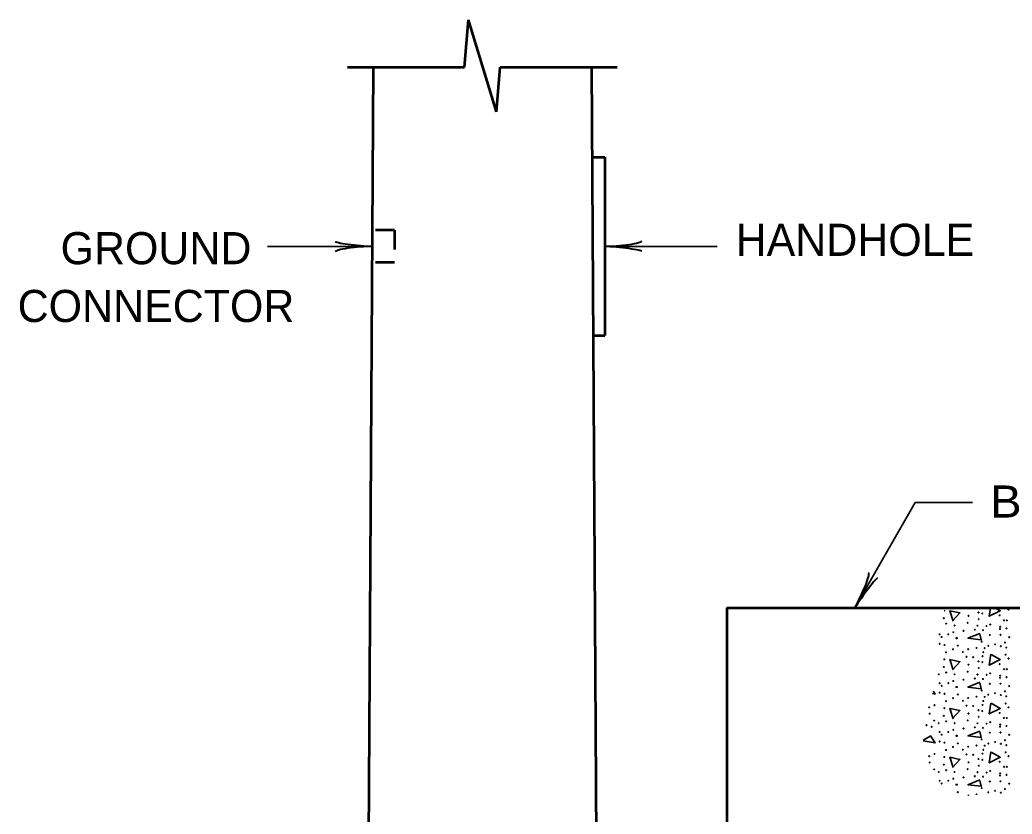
# Model space of a CAD drawing. Extents: x -35 to 821, y -23 to 522.
# Drawn here: x 313.6 to 406.3, y 208.5 to 282.7 of the extents above; entities that cross this region are included whole.
import ezdxf
from ezdxf.enums import TextEntityAlignment as Align

# ---------------------------------------------------------------- set-up
doc = ezdxf.new("R2010")
doc.units = 0
doc.header["$LTSCALE"] = 1.2
doc.linetypes.add('SHORT_DASHED', pattern=[2.7, 1.5, -1.2])
doc.layers.add('1', color=7, linetype='Continuous', lineweight=35)

msp = doc.modelspace()

# ---------------------------------------------------------------- linework, layer by layer
at = {"layer": '1', "lineweight": 53}
for p, q in [((355.139, 278.3), (355.526, 282.729)), ((358.12, 274.128), (355.526, 282.729)), ((344.212, 278.3), (355.139, 278.3)), ((346.612, 278.3), (346.008, 175.593)), ((358.12, 274.128), (358.485, 278.3)), ((358.485, 278.3), (369.412, 278.3)), ((367.012, 278.3), (367.617, 175.564)), ((367.062, 269.897), (368.262, 269.897)), ((368.262, 269.897), (368.262, 253.242)), ((367.16, 253.242), (368.262, 253.242)), ((379.645, 227.82), (379.645, 144.588)), ((379.645, 227.82), (400.045, 227.82))]:
    msp.add_line(p, q, dxfattribs=at)
at = {"layer": '1', "linetype": 'SHORT_DASHED', "lineweight": 53}
for p, q in [((348.614, 263.07), (346.514, 263.07)), ((348.614, 263.07), (348.614, 260.07)), ((348.614, 260.07), (346.514, 260.07))]:
    msp.add_line(p, q, dxfattribs=at)
at = {"layer": '1'}
for p, q in [((346.514, 261.57), (336.727, 261.57)), ((368.262, 261.57), (378.744, 261.57)), ((398.723, 215.843), (398.007, 215.453))]:
    msp.add_line(p, q, dxfattribs=at)
for points in [[(391.622, 227.82), (397.262, 237.643), (402.619, 237.643)], [(400.787, 226.571), (400.499, 227.531), (401.435, 227.339), (400.763, 226.619)], [(404.697, 227.82), (405.203, 227.531), (404.171, 227.027), (404.284, 227.82)], [(403.307, 225.419), (402.179, 224.963), (403.427, 224.819), (403.307, 225.371)], [(404.363, 223.451), (405.203, 222.971), (404.171, 222.467), (404.315, 223.475)], [(400.787, 222.011), (400.499, 222.971), (401.435, 222.779), (400.763, 222.059)], [(403.307, 220.859), (402.179, 220.403), (403.427, 220.259), (403.307, 220.811)], [(398.868, 219.799), (399.107, 219.755), (398.927, 220.035)], [(404.363, 218.891), (405.203, 218.411), (404.171, 217.907), (404.315, 218.915)], [(400.787, 217.451), (400.499, 218.411), (401.435, 218.219), (400.763, 217.499)], [(403.307, 216.299), (402.179, 215.843), (403.427, 215.699), (403.307, 216.251)], [(398.006, 215.397), (399.107, 215.195), (398.675, 215.867)], [(404.363, 214.331), (405.203, 213.851), (404.171, 213.347), (404.315, 214.355)], [(400.787, 212.891), (400.499, 213.851), (401.435, 213.659), (400.763, 212.939)], [(403.307, 211.739), (402.179, 211.283), (403.427, 211.139), (403.307, 211.691)]]:
    msp.add_lwpolyline(points, dxfattribs=at)
at = {"layer": '1', "lineweight": 53}
msp.add_lwpolyline([(400.045, 227.82), (410.845, 227.82), (412.644, 226.02), (415.449, 211.896)], dxfattribs=at)
at = {"layer": '1'}
for centre in [(402.665, 227.766), (403.174, 227.368), (403.524, 227.289), (405.973, 227.638), (399.93, 226.843), (400.153, 226.334), (402.157, 226.414), (402.236, 227.066), (403.19, 226.748), (404.256, 226.254), (405.146, 227.114), (405.544, 226.636), (405.814, 226.636), (399.532, 225.338), (400.344, 225.338), (400.821, 225.529), (400.932, 226.159), (401.759, 225.656), (402.825, 225.767), (403.079, 226.143), (403.588, 225.719), (403.922, 226.111), (404.224, 225.274), (405.178, 225.831), (405.194, 226.032), (405.226, 225.29), (405.783, 225.894), (399.532, 224.447), (399.723, 225.083), (401.091, 224.972), (401.155, 224.972), (403.461, 224.653), (404.717, 224.399), (405.639, 224.574), (406.037, 225.067), (399.994, 224.335), (400.137, 223.651), (400.789, 223.938), (401.234, 224.272), (401.711, 223.683), (402.204, 223.954), (402.984, 224.065), (403.62, 223.667), (403.747, 224.049), (404.081, 224.256), (405.258, 224.224), (405.703, 223.429), (405.767, 224.097), (399.978, 222.999), (402.045, 223.238), (402.236, 222.506), (402.665, 223.206), (403.174, 222.808), (403.524, 222.729), (403.54, 223.301), (405.146, 222.554), (405.973, 223.078), (399.453, 221.599), (399.93, 222.283), (400.153, 221.774), (400.932, 221.599), (402.157, 221.854), (403.079, 221.583), (403.19, 222.188), (404.256, 221.694), (405.544, 222.076), (405.814, 222.076), (399.532, 220.778), (400.344, 220.778), (400.821, 220.969), (401.759, 221.096), (402.825, 221.207), (403.588, 221.159), (403.922, 221.551), (404.224, 220.714), (405.178, 221.271), (405.194, 221.472), (405.226, 220.73), (405.783, 221.334), (399.532, 219.887), (399.723, 220.523), (399.994, 219.775), (401.091, 220.412), (401.155, 220.412), (401.234, 219.712), (403.461, 220.093), (404.717, 219.839), (405.639, 220.014), (406.037, 220.507), (400.137, 219.091), (400.789, 219.378), (401.711, 219.123), (402.204, 219.394), (402.984, 219.505), (403.62, 219.107), (403.747, 219.489), (404.081, 219.696), (405.258, 219.664), (405.703, 218.869), (405.767, 219.537), (398.562, 218.518), (398.61, 217.93), (399.055, 218.725), (399.978, 218.439), (402.045, 218.678), (402.236, 217.946), (402.665, 218.646), (403.174, 218.248), (403.524, 218.169), (403.54, 218.741), (405.146, 217.994), (405.973, 218.518), (399.024, 217.278), (399.453, 217.039), (399.93, 217.723), (400.153, 217.214), (400.932, 217.039), (402.157, 217.294), (403.079, 217.023), (403.19, 217.628), (403.922, 216.991), (404.256, 217.134), (405.544, 217.516), (405.814, 217.516), (398.308, 216.848), (398.785, 216.695), (399.532, 216.218), (400.344, 216.218), (400.821, 216.409), (401.759, 216.536), (402.825, 216.647), (403.588, 216.599), (404.224, 216.154), (405.178, 216.711), (405.194, 216.912), (405.226, 216.17), (405.783, 216.774), (399.532, 215.327), (399.723, 215.963), (399.994, 215.215), (401.091, 215.852), (401.155, 215.852), (401.234, 215.152), (403.461, 215.533), (404.081, 215.136), (404.717, 215.279), (405.258, 215.104), (405.639, 215.454), (406.037, 215.947), (399.055, 214.165), (400.137, 214.531), (400.789, 214.818), (401.711, 214.563), (402.204, 214.834), (402.984, 214.945), (403.54, 214.181), (403.62, 214.547), (403.747, 214.929), (405.703, 214.309), (405.767, 214.977), (398.562, 213.958), (398.61, 213.37), (399.978, 213.879), (402.045, 214.118), (402.236, 213.386), (402.665, 214.086), (403.174, 213.688), (403.524, 213.609), (405.146, 213.434), (405.973, 213.958), (399.024, 212.718), (399.453, 212.479), (399.93, 213.163), (400.153, 212.654), (400.932, 212.479), (402.157, 212.734), (403.079, 212.463), (403.19, 213.068), (403.922, 212.431), (404.256, 212.574), (405.194, 212.352), (405.544, 212.956), (405.814, 212.956), (399.532, 211.658), (399.723, 211.403), (400.344, 211.658), (400.821, 211.849), (401.759, 211.976), (402.825, 212.087), (403.588, 212.039), (404.224, 211.594), (405.178, 212.151), (405.226, 211.61), (405.783, 212.214), (406.037, 211.387), (401.091, 211.292), (401.155, 211.292), (401.234, 210.592), (403.461, 210.973), (404.081, 210.576), (404.717, 210.719), (405.258, 210.544), (405.639, 210.894)]:
    msp.add_circle(centre, 0.0318, dxfattribs=at)
for centre, start, end in [((399.978, 227.559), 253.75586, 77.13253), ((402.045, 227.798), 134.48926, 45.51074), ((402.204, 210.274), 14.9342, 178.72641), ((402.984, 210.385), 8.19211, 187.61765)]:
    msp.add_arc(centre, 0.0318, start, end, dxfattribs=at)
at = {"layer": '1', "lineweight": 40}
for centre, major_axis, ratio, start_param, end_param in [((345.204, 261.238), (2.143, 0.187), 0.122415, 0.896353, 3.141593), ((345.204, 261.238), (2.143, 0.187), 0.122415, 0.896353, 3.141593), ((345.169, 261.823), (2.108, -0.211), 0.07063, 3.140715, 5.41811), ((345.169, 261.823), (2.108, -0.211), 0.07063, 3.140715, 5.41811), ((369.606, 261.316), (-2.108, 0.211), 0.07063, 3.140715, 5.41811), ((369.571, 261.901), (-2.143, -0.187), 0.122415, 0.896353, 3.141593), ((391.987, 229.121), (-0.904, -1.952), 0.122415, 0.896353, 3.141593), ((391.987, 229.121), (-0.904, -1.952), 0.122415, 0.896353, 3.141593), ((392.512, 228.86), (1.232, 1.723), 0.07063, 6.282307, 8.559703), ((392.512, 228.86), (1.232, 1.723), 0.07063, 6.282307, 8.559703)]:
    msp.add_ellipse(centre, major_axis=major_axis, ratio=ratio, start_param=start_param, end_param=end_param, dxfattribs=at)

# ---------------------------------------------------------------- texts
at = {"layer": '1'}
msp.add_text('HANDHOLE', height=3, dxfattribs=at).set_placement((380.477, 260.685))
for s, p in [('GROUND', (326.32, 259.903)), ('CONNECTOR', (326.32, 254.503))]:
    msp.add_text(s, height=3, dxfattribs=at).set_placement(p, align=Align.CENTER)
at = {"layer": '1', "width": 1.1}
msp.add_text('BRIDGE PARAPET', height=3, dxfattribs=at).set_placement((404.254, 236.24))

doc.saveas('drawing.dxf')
